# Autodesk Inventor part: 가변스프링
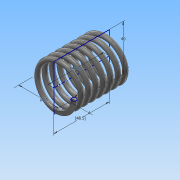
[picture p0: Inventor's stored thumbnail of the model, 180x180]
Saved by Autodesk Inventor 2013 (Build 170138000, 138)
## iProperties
Created: 2014-12
Part Number: 가변스프링
Material: 강철, 탄소
Document SubType Name: Modeling
Designer: Administrator
Density: 7.87 g/cm^3
Mass: 80.13 g
Surface Area: 103.216 cm^2
Volume: 10.1817 cm^3
Author: Administrator
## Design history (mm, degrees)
sketch "스케치1"
  geometry: L1 (0, 0)-(0, 48.5); L2 (0, 0)-(17.5, 0); L3 (0, 48.5)-(17.5, 48.5); C1 r 2 at (17.5, 0)
  constraints: 6 end point, 2 parallel, 1 centre point, 1 horizontal alignment, 1 perpendicular, 1 vertical
  dimensions: "d0" = 48.5 distance of L1.start L1.end (derived); "d1" = 4 diameter of C1; "d2" = 35 diameter of L2.end L1
feature "코일1" sketch "스케치1" pitch "d3" = 10; turns "d5" = 7.5; dims "d4" = 48.5 (= d0), "d6" = 0, angle "d7" = 90 deg, angle "d8" = 90 deg, "d9" = 0, "d10" = 0
sketch "스케치2"
  geometry: L1 (48.5, 20)-(0, 20); L2 (0, 20)-(0, -20); L3 (0, -20)-(48.5, -20); L4 (48.5, -20)-(48.5, 20); 2 further points
  constraints: 8 end point, 2 parallel, 1 coincident, 1 horizontal, 1 midpoint, 1 perpendicular
  dimensions: "d11" = 40 distance of L3.end L1.start; "d13" = 48.5 distance of L2.end L3.end (derived)
extrude "돌출1" sketch "스케치2" stored distance "d14" = 55; taper "d15" = 0 deg
node "솔리드1"
